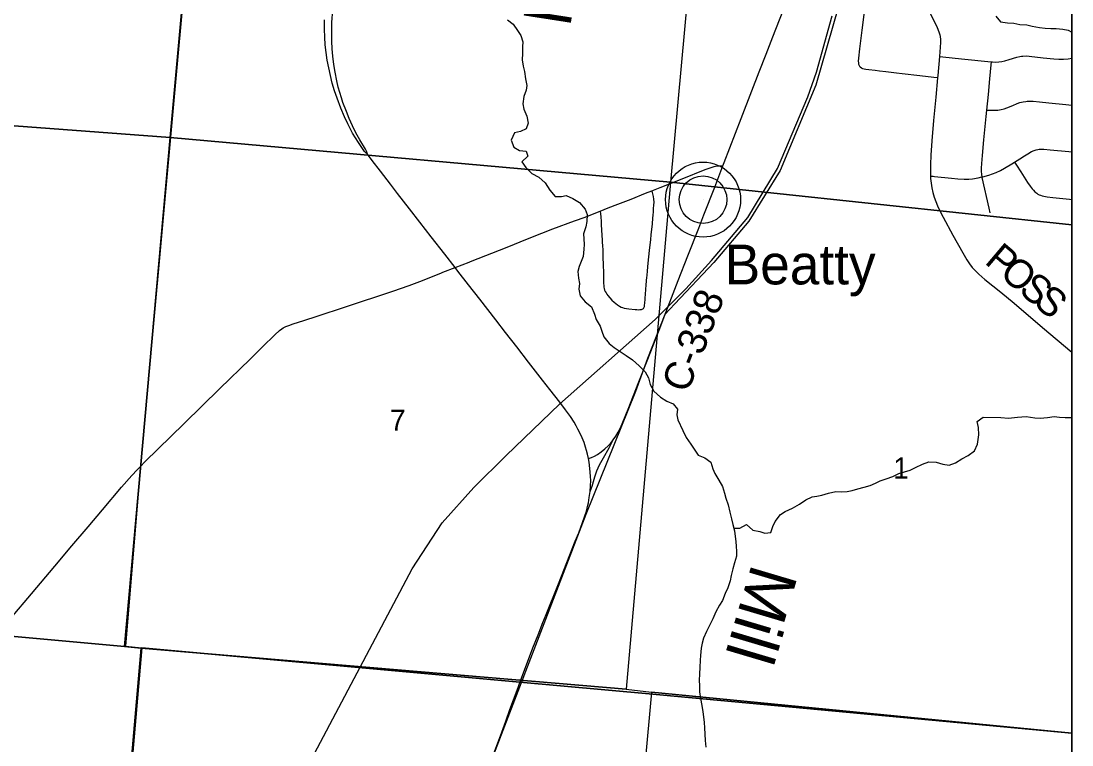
# Model space of a CAD drawing. Extents: x 0 to 1134, y 0 to 440.
# Drawn here: x 476.5 to 539, y 112.7 to 155.8 of the extents above; entities that cross this region are included whole.
import ezdxf

# ---------------------------------------------------------------- set-up
doc = ezdxf.new("R2010")
doc.units = 0
for name, color, linetype in [('Default', 7, 'Continuous'), ('GM_X_County_Road', 7, 'Continuous'), ('GM_X_County_Road_Text', 7, 'Continuous'), ('GM_X_Minor_River', 7, 'Continuous'), ('GM_X_Minor_River_Text', 7, 'Continuous'), ('GM_X_Rail_Line', 7, 'Continuous'), ('GM_X_Section', 7, 'Continuous'), ('GM_X_Section_Text', 7, 'Continuous'), ('GM_X_Township', 7, 'Continuous'), ('GM_X_Township_Road', 7, 'Continuous'), ('GM_X_Unincorporated', 7, 'Continuous'), ('GM_X_Unincorporated_Location', 7, 'Continuous'), ('GM_X_Unincorporated_Text', 7, 'Continuous'), ('GM_X_US_Route', 7, 'Continuous'), ('SH_Cut_Line', 7, 'Continuous'), ('SH_Text', 7, 'Continuous')]:
    doc.layers.add(name, color=color, linetype=linetype)

msp = doc.modelspace()

# ---------------------------------------------------------------- linework, layer by layer
at = {"layer": 'Default'}
for points in [[(539, 143.681), (539, 174.139), (517.859, 176.283), (515.105, 146.205)], [(539, 113.435), (539, 143.681), (515.105, 146.205), (512.465, 116.052), (513.985, 115.883)], [(539, 84.477), (539, 113.435), (513.985, 115.883), (511.315, 86.803)]]:
    msp.add_lwpolyline(points, close=True, dxfattribs=at)
at = {"layer": 'GM_X_County_Road'}
msp.add_line((502.287, 141.138), (503.123, 141.464), dxfattribs=at)
for points in [[(518.225, 147.183), (518.307, 147.392), (519.314, 149.998), (519.952, 151.649), (520.388, 152.779), (520.796, 153.819), (521.195, 154.863), (521.806, 156.424), (522.646, 158.596), (523.436, 160.658)], [(529.986, 157.209), (530.108, 157.037), (530.203, 156.881), (530.345, 156.645), (530.568, 156.238), (530.824, 155.741), (530.983, 155.405), (531.085, 155.147), (531.137, 154.971), (531.154, 154.881), (531.175, 154.699), (531.177, 154.515), (531.161, 154.237), (531.114, 153.692)], [(531.114, 153.692), (531.018, 152.565), (531.005, 152.42)], [(531.005, 152.42), (530.898, 151.265), (530.761, 149.873), (530.654, 148.664), (530.598, 147.828), (530.574, 147.269), (530.573, 146.801), (530.581, 146.577)], [(510.926, 144.498), (511.395, 144.684), (511.977, 144.911), (512.76, 145.212), (513.627, 145.551), (513.995, 145.696), (514.494, 145.893), (515.794, 146.407), (517.179, 146.961), (517.526, 147.093), (517.702, 147.144), (517.786, 147.163), (517.854, 147.177), (517.916, 147.183), (517.993, 147.183), (518.163, 147.183), (518.225, 147.183)], [(511.658, 130.831), (511.701, 130.884), (511.859, 131.113), (512, 131.352), (512.127, 131.598), (512.276, 131.938), (512.583, 132.717), (513.217, 134.331), (513.711, 135.587), (514.422, 137.411), (514.822, 138.455), (515.261, 139.583), (515.567, 140.364), (516.145, 141.838), (516.79, 143.485), (517.093, 144.266), (517.735, 145.916), (518.225, 147.183)], [(530.581, 146.577), (530.586, 146.427), (530.613, 146.147), (530.659, 145.869), (530.722, 145.595), (530.804, 145.325), (530.899, 145.061), (531.003, 144.801), (531.118, 144.545), (531.333, 144.13), (531.917, 143.067), (532.501, 142.004), (532.739, 141.602), (532.893, 141.366), (533.064, 141.142), (533.254, 140.933), (533.457, 140.739), (533.812, 140.434), (534.756, 139.672), (535.551, 139.024), (537.255, 137.574), (539, 136.096)], [(503.123, 141.464), (503.206, 141.497), (505.376, 142.347), (506.587, 142.834), (507.453, 143.178), (508.107, 143.429), (509.396, 143.918), (510.033, 144.138), (510.567, 144.356), (510.926, 144.498)], [(483.54, 129.279), (483.561, 129.3), (483.83, 129.57), (486.164, 131.851), (488.293, 133.94), (490.097, 135.696), (490.829, 136.415), (491.562, 137.132), (491.834, 137.384), (491.98, 137.495), (492.057, 137.543), (492.22, 137.627), (492.391, 137.698), (492.653, 137.792), (493.274, 137.99), (494.075, 138.242), (495.756, 138.8), (498.588, 139.739), (499.557, 140.076), (500.343, 140.371), (501.473, 140.82)], [(501.473, 140.82), (501.556, 140.853), (502.287, 141.138)], [(510.231, 129.769), (510.403, 129.83), (510.575, 129.909), (510.757, 130.009), (510.984, 130.169), (511.198, 130.345), (511.402, 130.534), (511.527, 130.669), (511.658, 130.831)], [(510.325, 127.814), (510.439, 128.14), (510.523, 128.401), (510.607, 128.682), (510.725, 129.037), (510.801, 129.225), (510.858, 129.358), (510.952, 129.535), (511.115, 129.811), (511.461, 130.413), (511.544, 130.581), (511.658, 130.831)], [(474.982, 119.252), (475.874, 120.31), (477.076, 121.736), (478.456, 123.377), (479.485, 124.582), (480.449, 125.721), (481.294, 126.716), (482.442, 128.065), (483.054, 128.768), (483.37, 129.109), (483.54, 129.279)]]:
    msp.add_lwpolyline(points, dxfattribs=at)
at = {"layer": 'GM_X_Minor_River'}
for points in [[(505.408, 155.871), (505.747, 155.618), (506.005, 155.241), (506.207, 154.944), (506.318, 154.556), (506.304, 154.261), (506.29, 153.874), (506.276, 153.499), (506.341, 153.112), (506.407, 152.804), (506.483, 152.36), (506.548, 151.973), (506.523, 151.677), (506.373, 151.303), (506.324, 150.871), (506.378, 150.552), (506.557, 150.141)], [(534.474, 156.088), (534.744, 155.744), (535.163, 155.684), (535.549, 155.67), (535.9, 155.599), (536.32, 155.562), (536.637, 155.491), (537.068, 155.408), (537.396, 155.372), (537.737, 155.358), (538.066, 155.355), (538.451, 155.318), (538.769, 155.259), (539, 155.141)], [(506.557, 150.141), (506.633, 149.731), (506.517, 149.391), (506.176, 149.234), (505.812, 149.146), (505.616, 148.704), (505.772, 148.305), (506.11, 148.097), (506.519, 148.049), (506.607, 147.752), (506.264, 147.414), (506.5, 147.094), (506.861, 146.738), (507.268, 146.519), (507.651, 146.175), (507.92, 145.741), (508.235, 145.363), (508.621, 145.36), (508.905, 145.415), (509.289, 145.242), (509.685, 145), (510.034, 144.611), (510.145, 144.291), (510.13, 143.882), (510.06, 143.564), (509.932, 143.133), (509.952, 142.848), (509.961, 142.507), (509.948, 142.223), (509.899, 141.791), (509.668, 141.201), (509.586, 140.906), (509.64, 140.496), (509.683, 140.177), (509.646, 139.859), (509.734, 139.449), (510.026, 139.094), (510.41, 138.796), (510.588, 138.362), (510.677, 138.043), (510.912, 137.643), (511.023, 137.347), (511.146, 137.005), (511.449, 136.616), (511.754, 136.386), (512.115, 136.133), (512.477, 135.903), (512.838, 135.65), (513.244, 135.294), (513.593, 134.928), (513.806, 134.585), (513.905, 134.186), (514.118, 133.787), (514.501, 133.431), (514.885, 133.19), (515.27, 133.039), (515.528, 132.707), (515.492, 132.377), (515.546, 132.081), (515.847, 131.448)], [(533.458, 131.191), (533.44, 131.619), (533.363, 131.972), (533.705, 132.231), (534.772, 132.223), (535.225, 132.185), (535.759, 132.227), (536.282, 132.268), (536.792, 132.196), (537.098, 132.182), (537.552, 132.224), (537.938, 132.267), (538.267, 132.242), (538.585, 132.217), (538.993, 132.225), (539, 132.225)], [(515.847, 131.448), (516.029, 131.027), (516.321, 130.638), (516.556, 130.282), (516.746, 129.985), (517.154, 129.81), (517.504, 129.556), (517.625, 129.168), (517.736, 128.882), (517.982, 128.492), (518.194, 128.103), (518.327, 127.715), (518.403, 127.418), (518.536, 127.019), (518.645, 126.596), (518.732, 126.186), (518.82, 125.843), (518.918, 125.467), (518.961, 125.148), (518.992, 124.851), (519.023, 124.544), (519.043, 124.259), (519.029, 123.975), (518.923, 123.577), (518.806, 123.214), (518.711, 122.817), (518.662, 122.51), (518.511, 122.09), (518.36, 121.739), (518.197, 121.342), (518.023, 121.048), (517.804, 120.652), (517.618, 120.244), (517.467, 119.916), (517.247, 119.497), (517.062, 119.1), (516.99, 118.794), (516.931, 118.498), (516.892, 118.066), (516.878, 117.782), (516.851, 117.35), (516.836, 116.963), (516.821, 116.565), (516.841, 116.268), (516.837, 115.904), (516.89, 115.505), (516.966, 115.095), (517.03, 114.707), (517.062, 114.422), (517.104, 114.08), (517.135, 113.75), (517.143, 113.386), (517.173, 113.01), (517.203, 112.611)], [(518.875, 125.632), (519.238, 125.634), (519.627, 125.847), (520.01, 125.524), (520.429, 125.429), (520.724, 125.346), (521.076, 125.377), (521.193, 125.74), (521.333, 126.034), (521.643, 126.441), (521.929, 126.62), (522.363, 126.821), (522.774, 127.055), (523.152, 127.325), (523.528, 127.503), (523.813, 127.534), (524.12, 127.599), (524.508, 127.709), (524.94, 127.807), (525.281, 127.793), (525.611, 127.812), (525.918, 127.877), (526.26, 127.976), (526.624, 128.064), (526.989, 128.174), (527.297, 128.319), (527.594, 128.452), (527.936, 128.574), (528.335, 128.706), (528.7, 128.885), (529.031, 128.984), (529.373, 129.094), (529.692, 129.239), (530.103, 129.44), (530.479, 129.572), (530.922, 129.556), (531.319, 129.45), (531.682, 129.378), (532.058, 129.522), (532.447, 129.757), (532.824, 129.958), (533.201, 130.239), (533.376, 130.636), (533.458, 131.191)]]:
    msp.add_lwpolyline(points, dxfattribs=at)
at = {"layer": 'GM_X_Rail_Line'}
for points in [[(538.46, 190.872), (531.264, 175.625), (529.455, 171.744), (523.761, 151.987), (521.638, 146.912), (519.773, 143.896), (517.683, 141.431), (515.36, 138.979), (514.776, 138.349), (513.736, 135.72), (513.018, 133.756), (510.064, 126.441), (504.279, 111.389), (503.424, 109.358), (496.783, 96.163), (485.546, 73.661), (478.157, 58.904), (470.789, 44.152), (463.212, 28.991)], [(451.182, 30.018), (458.42, 44.067), (467.032, 60.601), (479.671, 85.012), (485.129, 95.275), (494.091, 112.577), (499.726, 123.224), (501.511, 125.956), (503.402, 128.057), (505.327, 129.949), (508.502, 133.012), (514.195, 138.036), (516.017, 139.869), (517.553, 141.551), (519.704, 144.119), (521.477, 147.018), (523.27, 151.286), (523.793, 152.748), (524.72, 156.111)]]:
    msp.add_lwpolyline(points, dxfattribs=at)
at = {"layer": 'GM_X_Section'}
for points in [[(458.022, 181.403), (488.076, 178.987), (485.322, 148.876), (454.792, 151.155)], [(488.076, 178.987), (517.859, 176.283), (515.105, 146.205), (485.322, 148.876)], [(454.792, 151.155), (485.322, 148.876), (482.612, 118.597), (452.931, 121.284), (452.262, 121.34)], [(515.105, 146.205), (512.465, 116.052), (483.61, 118.491), (482.612, 118.597), (485.322, 148.876)], [(452.931, 121.284), (482.612, 118.597), (483.61, 118.491), (481.064, 89.331), (450.756, 92.234)], [(483.61, 118.491), (512.465, 116.052), (513.985, 115.883), (511.315, 86.803), (481.064, 89.331)]]:
    msp.add_lwpolyline(points, close=True, dxfattribs=at)
at = {"layer": 'GM_X_Township'}
msp.add_lwpolyline([(487.542, 173.065), (483.554, 129.317), (482.679, 118.615), (483.64, 118.514), (482.383, 104.033), (478.487, 59.504), (477.008, 43.588)], dxfattribs=at)
at = {"layer": 'GM_X_Township_Road'}
for points in [[(531.005, 152.42), (530.77, 152.446), (529.944, 152.538), (529.593, 152.582), (529.254, 152.622), (528.895, 152.666), (528.561, 152.703), (527.919, 152.783), (527.548, 152.824), (527.286, 152.856), (526.917, 152.889), (526.733, 152.914), (526.641, 152.928), (526.551, 152.948), (526.469, 152.99), (526.402, 153.054), (526.353, 153.133), (526.322, 153.22), (526.306, 153.311), (526.302, 153.404), (526.316, 153.589), (526.379, 154.143), (526.516, 155.256), (526.645, 156.337)], [(531.114, 153.692), (531.306, 153.671), (532.416, 153.553), (534.196, 153.376)], [(534.196, 153.376), (534.179, 153.196), (534.095, 152.354), (534.004, 151.427), (533.907, 150.506)], [(534.196, 153.376), (534.267, 153.369), (534.453, 153.359), (534.639, 153.363), (534.819, 153.384), (535.004, 153.426), (535.271, 153.505), (535.714, 153.647), (535.895, 153.691), (535.986, 153.707), (536.079, 153.717), (536.265, 153.72), (536.45, 153.709), (537.282, 153.613), (537.929, 153.541), (538.208, 153.524), (538.486, 153.527), (538.765, 153.551), (539, 153.587)], [(533.907, 150.506), (534.034, 150.498), (534.22, 150.487), (534.407, 150.488), (534.593, 150.505), (534.776, 150.537), (534.955, 150.582), (535.129, 150.639), (535.47, 150.78), (535.728, 150.889), (535.906, 150.948), (536.086, 150.989), (536.257, 151.017), (536.333, 151.024), (536.505, 151.03), (536.687, 151.024), (537.06, 150.995), (537.618, 150.94), (538.639, 150.834), (539, 150.794)], [(533.907, 150.506), (533.867, 150.124), (533.735, 148.727), (533.649, 147.792), (533.615, 147.327), (533.599, 147.049), (533.598, 146.862), (533.612, 146.675), (533.637, 146.528)], [(535.585, 147.408), (535.733, 147.501), (535.905, 147.611), (536.183, 147.788), (536.369, 147.908), (536.599, 148.037), (536.752, 148.104), (536.872, 148.133), (536.963, 148.155), (537.055, 148.17), (537.147, 148.178), (537.333, 148.179), (537.704, 148.145), (538.815, 148.033), (539, 148.012)], [(533.637, 146.528), (533.685, 146.538), (534.043, 146.64), (534.482, 146.794), (534.737, 146.906), (534.984, 147.037), (535.422, 147.305), (535.585, 147.408)], [(535.585, 147.408), (535.702, 147.224), (535.963, 146.822), (536.353, 146.2), (536.511, 145.969), (536.625, 145.826), (536.702, 145.737), (536.796, 145.648), (536.906, 145.554), (536.971, 145.509), (537.052, 145.465), (537.133, 145.436), (537.231, 145.404), (537.32, 145.379), (537.527, 145.347), (537.869, 145.302), (538.844, 145.2), (539, 145.184)], [(530.581, 146.577), (530.729, 146.564), (530.821, 146.555), (531.839, 146.444), (532.21, 146.412), (532.582, 146.396), (532.853, 146.401), (533.073, 146.42), (533.412, 146.479), (533.637, 146.528)], [(533.637, 146.528), (533.643, 146.491), (534.05, 144.664), (534.111, 144.39)], [(510.926, 144.498), (510.938, 144.339), (510.951, 144.153), (510.975, 143.875), (510.988, 143.688), (511.015, 143.043), (511.035, 142.778), (511.046, 142.623), (511.055, 142.45), (511.072, 142.175), (511.088, 141.71), (511.1, 141.336), (511.114, 140.779), (511.123, 140.497), (511.123, 140.194), (511.132, 140.064), (511.137, 139.973), (511.155, 139.882), (511.184, 139.793), (511.223, 139.708), (511.268, 139.626), (511.317, 139.547), (511.372, 139.472), (511.49, 139.329), (511.616, 139.194), (511.753, 139.067), (511.947, 138.918), (512.006, 138.873), (512.079, 138.83), (512.168, 138.784), (512.253, 138.751), (512.353, 138.721), (512.489, 138.699), (512.626, 138.677), (513.006, 138.642), (513.099, 138.633), (513.192, 138.629), (513.287, 138.631), (513.377, 138.644), (513.455, 138.674), (513.49, 138.699), (513.519, 138.739), (513.552, 138.82), (513.566, 138.911), (513.577, 139.003), (513.582, 139.087), (513.589, 139.183), (513.597, 139.308), (513.618, 139.557), (513.663, 140.109), (513.707, 140.567), (513.715, 140.652), (513.724, 140.755), (513.729, 140.847), (513.741, 140.941), (513.782, 141.406), (513.859, 142.15), (513.929, 142.801), (513.961, 143.08), (514.025, 143.745), (514.058, 144.074), (514.073, 144.255), (514.088, 144.458), (514.099, 144.653), (514.113, 144.84), (514.125, 145.026), (514.117, 145.2), (514.095, 145.358), (514.025, 145.595), (513.995, 145.696)]]:
    msp.add_lwpolyline(points, dxfattribs=at)
at = {"layer": 'GM_X_Unincorporated'}
for points in [[(487.542, 173.065), (483.554, 129.317), (482.679, 118.615), (483.64, 118.514), (506.135, 116.476), (513.831, 115.79), (539, 113.439), (539, 295.833)], [(539, 17.107), (539, 113.439), (513.831, 115.79), (506.135, 116.476), (483.64, 118.514), (482.383, 104.033), (478.487, 59.504), (477.008, 43.588)]]:
    msp.add_lwpolyline(points, dxfattribs=at)
for radius in [2.232, 1.415]:
    msp.add_circle((517.043, 145.174), radius, dxfattribs=at)
at = {"layer": 'GM_X_Unincorporated_Location'}
msp.add_line((517.043, 145.174), (517.043, 145.174), dxfattribs=at)
at = {"layer": 'GM_X_US_Route'}
for points in [[(497.071, 147.887), (497.042, 147.99), (497.022, 148.054), (496.958, 148.178), (496.607, 148.733), (496.382, 149.143), (496.176, 149.563), (495.988, 149.991), (495.814, 150.424), (495.611, 150.959), (495.518, 151.231), (495.424, 151.556), (495.335, 151.872), (495.246, 152.232), (495.148, 152.75), (495.069, 153.218), (495.01, 153.701), (494.975, 154.15), (494.955, 154.604), (494.941, 155.147), (494.955, 155.709), (495, 156.468), (495.106, 157.598), (495.162, 158.303)], [(497.071, 147.887), (496.978, 147.961), (496.899, 148.044), (496.815, 148.153), (496.687, 148.345), (496.529, 148.582), (496.356, 148.848), (496.188, 149.134), (495.907, 149.674), (495.709, 150.094), (495.491, 150.607), (495.261, 151.216), (495.111, 151.656), (494.979, 152.101), (494.862, 152.551), (494.762, 153.005), (494.678, 153.462), (494.612, 153.922), (494.562, 154.384), (494.528, 154.847), (494.512, 155.311), (494.514, 155.869)], [(502.287, 141.138), (501.673, 141.929), (500.859, 142.969), (500.183, 143.837), (499.572, 144.626), (498.857, 145.549), (498.433, 146.101), (497.841, 146.87), (497.357, 147.497), (497.071, 147.887)], [(510.325, 127.814), (510.349, 128.163), (510.356, 128.444), (510.347, 128.725), (510.309, 129.191), (510.262, 129.563), (510.231, 129.769), (510.176, 130.031), (510.116, 130.251), (510.053, 130.451), (510.009, 130.582), (509.958, 130.73), (509.845, 130.999), (509.707, 131.295), (509.596, 131.523), (509.49, 131.724), (509.367, 131.936), (509.145, 132.272), (508.864, 132.666), (508.514, 133.12), (507.917, 133.889), (507.488, 134.442), (506.659, 135.512), (505.954, 136.414), (505.283, 137.282), (504.711, 138.022), (504.233, 138.634), (503.749, 139.255), (503.088, 140.099), (502.452, 140.927), (502.287, 141.138)], [(509.442, 124.865), (509.641, 125.366), (509.874, 125.977), (510.012, 126.362), (510.1, 126.647), (510.169, 126.914), (510.217, 127.142), (510.273, 127.451), (510.308, 127.696), (510.325, 127.814)], [(504.275, 111.397), (504.374, 111.654), (504.626, 112.33), (505.06, 113.508), (505.296, 114.159), (505.553, 114.851), (506.032, 116.165), (506.142, 116.46), (506.358, 117.039), (506.922, 118.52), (507.233, 119.299), (507.514, 120.018), (507.706, 120.508), (508.435, 122.333), (509.442, 124.865)]]:
    msp.add_lwpolyline(points, dxfattribs=at)
at = {"layer": 'SH_Cut_Line'}
msp.add_lwpolyline([(539, 17.107), (539, 425.107)], dxfattribs=at)
at = {"layer": 'SH_Text'}
msp.add_lwpolyline([(131, 425.107), (539, 425.107), (539, 17.107), (131, 17.107)], close=True, dxfattribs=at)

# ---------------------------------------------------------------- texts
at = {"layer": 'GM_X_County_Road_Text'}
for s, height, rotation, p in [('P', 1.705, 319.71077, (533.739, 141.423)), ('O', 1.705, 319.7114, (534.616, 140.679)), ('S', 1.705, 319.70896, (535.76, 139.709)), ('C-338', 1.7045, 68.96181, (516.125, 133.609)), ('S', 1.705, 319.70983, (536.638, 138.965))]:
    msp.add_text(s, height=height, rotation=rotation, dxfattribs=at).set_placement(p)
at = {"layer": 'GM_X_Minor_River_Text'}
for height, rotation, p in [(2.8401, 81.17673, (509.13, 155.388)), (2.8402, 253.45919, (519.969, 123.594))]:
    msp.add_text('Mill', height=height, rotation=rotation, dxfattribs=at).set_placement(p)
at = {"layer": 'GM_X_Section_Text'}
for s, p in [('7', (498.406, 131.427)), ('1', (528.356, 128.586))]:
    msp.add_text(s, height=1.256, rotation=0.00001, dxfattribs=at).set_placement(p)
at = {"layer": 'GM_X_Unincorporated_Text'}
msp.add_text('Beatty', height=2.3693, rotation=0.00001, dxfattribs=at).set_placement((518.331, 140.133))

doc.saveas('drawing.dxf')
